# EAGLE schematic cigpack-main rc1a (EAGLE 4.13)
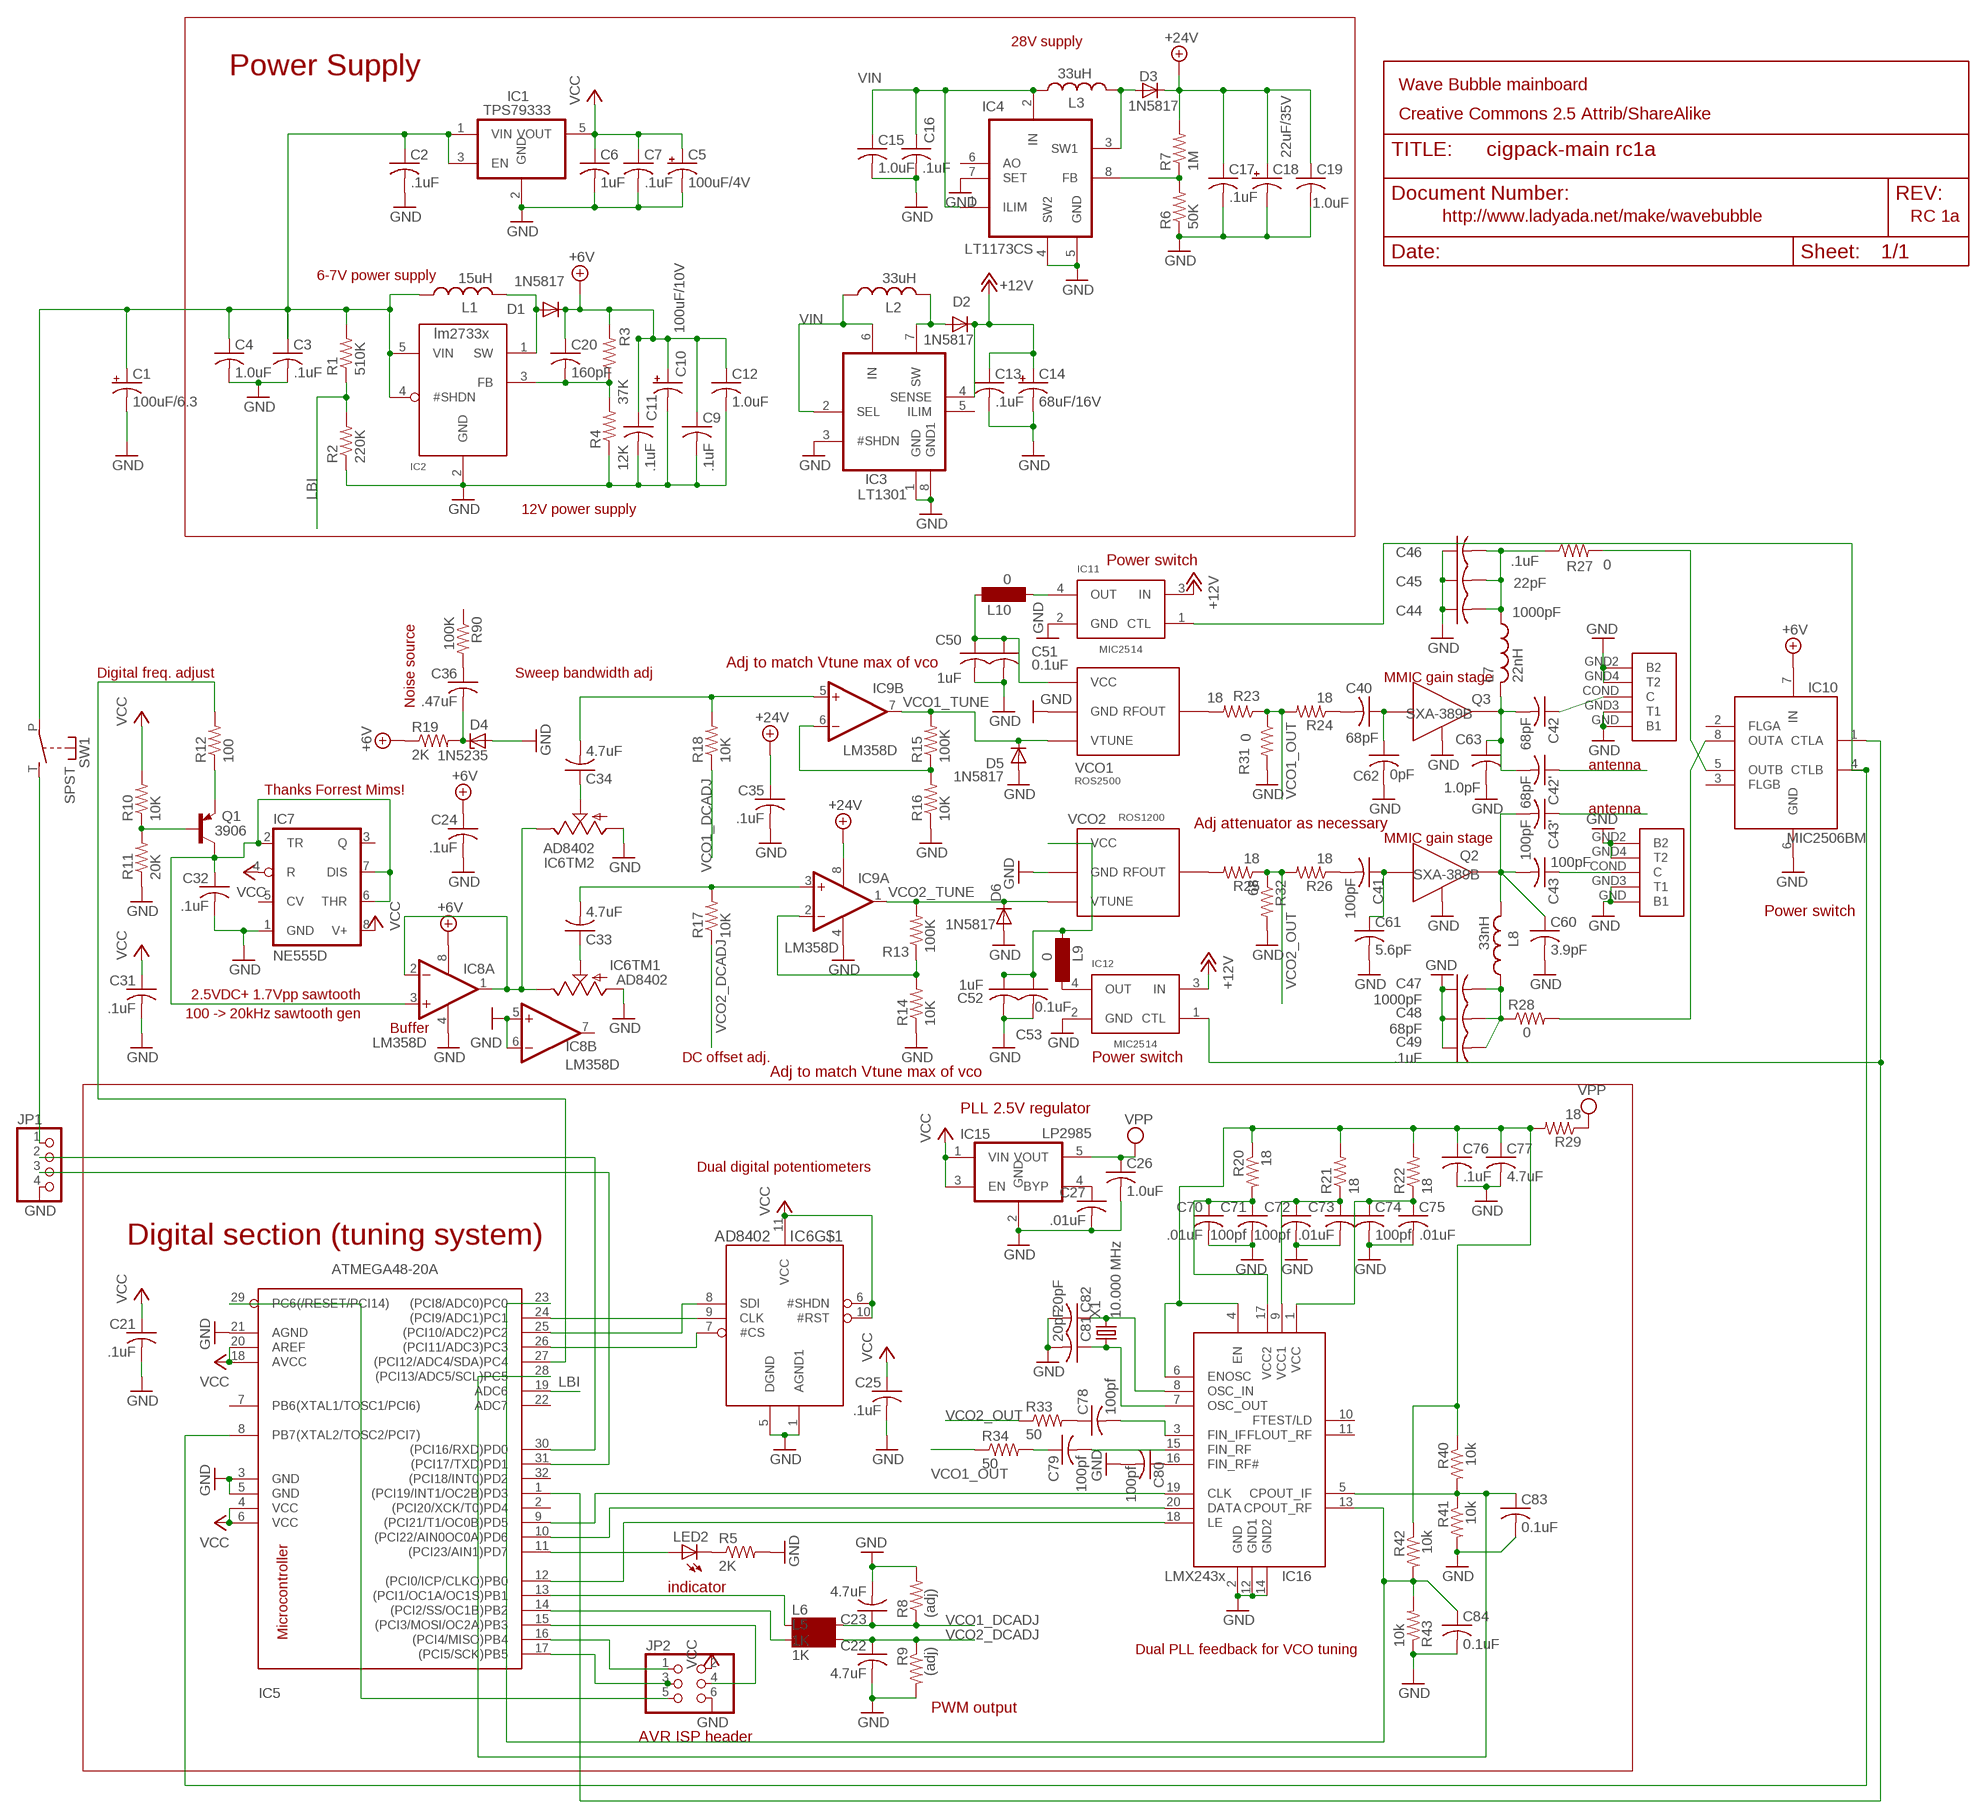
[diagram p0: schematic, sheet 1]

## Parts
C1  100uF/6.3  CPOL-USD  [PANASONIC_D]
C2  .1uF  C-USC1206  [C1206]
C3  .1uF  C-USC1206  [C1206]
C4  1.0uF  C-USC1206  [C1206]
C5  100uF/4V  CPOL-USD  [PANASONIC_D]
C6  1uF  C-USC1206  [C1206]
C7  .1uF  C-USC1206  [C1206]
C9  .1uF  C-USC1206  [C1206]
C10  100uF/10V  CPOL-USCT7343  [CT7343]
C11  .1uF  C-USC1206  [C1206]
C12  1.0uF  C-USC1206  [C1206]
C13  .1uF  C-USC1206  [C1206]
C14  68uF/16V  CPOL-USCT6032  [CT6032]
C15  1.0uF  C-USC1206  [C1206]
C16  .1uF  C-USC1206  [C1206]
C17  .1uF  C-USC1206  [C1206]
C18  22uF/35V  CPOL-USD/7343-31W  [D/7343-31W]
C19  1.0uF  C-USC1206  [C1206]
C20  160pF  C-USC1206  [C1206]
C21  .1uF  C-USC1206  [C1206]
C22  4.7uF  C-USC1206  [C1206]
C23  4.7uF  C-USC1206  [C1206]
C24  .1uF  C-USC1206  [C1206]
C25  .1uF  C-USC1206  [C1206]
C26  1.0uF  C-USC1206  [C1206]
C27  .01uF  C-USC0603  [C0603]
C31  .1uF  C-USC0603  [C0603]
C32  .1uF  C-USC1206  [C1206]
C33  4.7uF  C-USC1206  [C1206]
C34  4.7uF  C-USC1206  [C1206]
C35  .1uF  C-USC1206  [C1206]
C36  .47uF  C-USC1206  [C1206]
C40  68pF  C-USC0603  [C0603]
C41  100pF  C-USC0603  [C0603]
C42  68pF  C-USC0603  [C0603]
C42'  68pF  C-USC0603  [C0603]
C43  100pF  C-USC0603  [C0603]
C43'  100pF  C-USC0603  [C0603]
C44  1000pF  C-USC0603  [C0603]
C45  22pF  C-USC0603  [C0603]
C46  .1uF  C-USC1206  [C1206]
C47  1000pF  C-USC0603  [C0603]
C48  68pF  C-USC0603  [C0603]
C49  .1uF  C-USC1206  [C1206]
C50  1uF  C-USC1206  [C1206]
C51  0.1uF  C-USC1206  [C1206]
C52  1uF  C-USC1206  [C1206]
C53  0.1uF  C-USC1206  [C1206]
C60  3.9pF  C-USC0603  [C0603]
C61  5.6pF  C-USC0603  [C0603]
C62  0pF  C-USC0603  [C0603]
C63  1.0pF  C-USC0603  [C0603]
C70  .01uF  C-USC0603  [C0603]
C71  100pf  C-USC0603  [C0603]
C72  100pf  C-USC0603  [C0603]
C73  .01uF  C-USC0603  [C0603]
C74  100pf  C-USC0603  [C0603]
C75  .01uF  C-USC0603  [C0603]
C76  .1uF  C-USC0603  [C0603]
C77  4.7uF  C-USC0603  [C0603]
C78  100pf  C-USC0603  [C0603]
C79  100pf  C-USC0603  [C0603]
C80  100pf  C-USC0603  [C0603]
C81  20pF  C-USC0603  [C0603]
C82  20pF  C-USC0603  [C0603]
C83  0.1uF  C-USC1206  [C1206]
C84  0.1uF  C-USC1206  [C1206]
D1  1N5817  DIODE-SMB  [SMB]
D2  1N5817  DIODE-SMB  [SMB]
D3  1N5817  DIODE-SMB  [SMB]
D4  1N5235  ZENER-DIODESMB  [SMB]
D5  1N5817  DIODE-SMB  [SMB]
D6  1N5817  DIODE-SMB  [SMB]
IC1  TPS79333  TPS79XXX  [SOT23-5L]
IC2  LM2733  [SOT23-5L]
IC3  LT1301  [SO08]
IC4  LT1173CS  [SO08]
IC5  ATMEGA48-20A  [TQFP32-08]
IC6  AD8402  [SO14]
IC7  NE555D  [SO08]
IC8  LM358D  [SO08]
IC9  LM358D  [SO08]
IC10  MIC2506BM  [SO08]
IC11  MIC2514  [SOT23-5L]
IC12  MIC2514  [SOT23-5L]
IC15  LP2985  [SOT23-5L]
IC16  LMX243X  [TSSOP-20]
JP1  PINHD-1X4  [1X04]
JP2  PINHD-2X3  [2X03]
L1  15uH  L_CDRH  [CDRH6D28]
L2  33uH  L_CDRH  [CDRH6D28]
L3  33uH  L_CDRH  [CDRH6D28]
L5  1K  SM-1206  [SM-1206]
L6  1K  SM-1206  [SM-1206]
L7  22nH  L_0603  [0603]
L8  33nH  L_0603  [0603]
L9  0  SM-1206  [SM-1206]
L10  0  SM-1206  [SM-1206]
LED2  LEDCHIPLED_1206  [CHIPLED_1206]
Q1  3906  MMBT3906LT1SMD  [SOT23-BEC]
Q2  SXA-389B  MMIC_MIDPOWERGAIN  [SOT89]
Q3  SXA-389B  MMIC_MIDPOWERGAIN  [SOT89]
R1  510K  R-US_R1206  [R1206]
R2  220K  R-US_R1206  [R1206]
R3  37K  R-US_R1206  [R1206]
R4  12K  R-US_R1206  [R1206]
R5  2K  R-US_R1206  [R1206]
R6  50K  R-US_R1206  [R1206]
R7  1M  R-US_R1206  [R1206]
R8  (adj)  R-US_R1206  [R1206]
R9  (adj)  R-US_R1206  [R1206]
R10  10K  R-US_R1206  [R1206]
R11  20K  R-US_R1206  [R1206]
R12  100  R-US_R1206  [R1206]
R13  100K  R-US_R1206  [R1206]
R14  10K  R-US_R1206  [R1206]
R15  100K  R-US_R1206  [R1206]
R16  10K  R-US_R1206  [R1206]
R17  10K  R-US_R1206  [R1206]
R18  10K  R-US_R1206  [R1206]
R19  2K  R-US_R1206  [R1206]
R20  18  R-US_R0603  [R0603]
R21  18  R-US_R0603  [R0603]
R22  18  R-US_R0603  [R0603]
R23  18  R-US_R0603  [R0603]
R24  18  R-US_R0603  [R0603]
R25  18  R-US_R0603  [R0603]
R26  18  R-US_R0603  [R0603]
R27  0  R-US_M1206  [M1206]
R28  0  R-US_M1206  [M1206]
R29  18  R-US_R0603  [R0603]
R31  0  R-US_R0603  [R0603]
R32  68  R-US_R0603  [R0603]
R33  50  R-US_R0603  [R0603]
R34  50  R-US_R0603  [R0603]
R40  10k  R-US_R0603  [R0603]
R41  10k  R-US_R1206  [R1206]
R42  10k  R-US_R0603  [R0603]
R43  10k  R-US_R1206  [R1206]
R90  100K  R-US_R1206  [R1206]
SW1  SPST  [JUDCOSPST]
U$8  SMAANTENNA  [SMA-ANTENNA]
U$9  SMAANTENNA  [SMA-ANTENNA]
VCO1  ROS2500  VCOKG  [MINICIRCUITS_KG]
VCO2  ROS1200  VCOKG  [MINICIRCUITS_KG]
X1  10.000 MHz  CRYSTAL_CRYTALABMM  [ABMM]

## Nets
+6V: C9.1 C10.+ C11.1 C12.1 C20.1 C24.1 D1.C IC8.8(P:V+) IC10.7(IN) R3.2 R19.1
+12V: C13.1 C14.+ D2.C IC3.4(SENSE) IC11.3(IN) IC12.3(IN)
+24V: C17.1 C18.+ C19.1 C35.1 D3.C IC9.8(P:V+) R7.2
CLK: IC5.24((PCI9/ADC1)PC1) IC6.9(CLK)
CP_IF: C83.1 IC5.28((PCI13/ADC5/SCL)PC5) IC16.5(CPOUT_IF) R40.2 R41.1
CP_RF: C84.1 IC5.23((PCI8/ADC0)PC0) IC16.13(CPOUT_RF) R42.2 R43.2
FB: IC4.8(FB) R6.2 R7.1
GND: C1.- C2.2 C3.2 C4.2 C5.- C6.2 C7.2 C9.2 C10.- C11.2 C12.2 C13.2 C14.- C15.2 C16.2 C17.2 C18.- C19.2 C21.2 C22.2 C23.2 C24.2 C25.2 C26.2 C27.2 C31.2 C32.2 C35.2 C44.1 C45.1 C46.1 C47.1 C48.1 C49.1 C50.2 C51.2 C52.2 C53.2 C60.2 C61.2 C62.2 C63.2 C70.2 C71.2 C72.2 C73.2 C74.2 C75.2 C76.2 C77.2 C80.2 C81.2 C82.2 C83.2 C84.2 D4.A D5.A D6.A IC1.2(GND) IC2.2(GND) IC3.1(GND) IC3.3(#SHDN) IC3.8(GND1) IC4.4(SW2) IC4.5(GND) IC4.7(SET) IC5.3(GND) IC5.5(GND) IC5.21(AGND) IC6.1(AGND1) IC6.2(TM2:B) IC6.5(DGND) IC6.14(TM1:B) IC7.1(GND) IC8.4(P:V-) IC8.5(B:+IN) IC8.6(B:-IN) IC9.4(P:V-) IC10.6(GND) IC11.2(GND) IC12.2(GND) IC15.2(GND) IC16.2(GND) IC16.12(GND1) IC16.14(GND2) JP1.4 JP2.6 Q2.2(GND) Q3.2(GND) R2.1 R4.1 R5.2 R6.1 R8.2 R9.2 R11.1 R14.1 R16.1 R31.2 R32.2 R41.2 R43.1 U$8.GND2(B2) U$8.GND3(T1) U$8.GND4(T2) U$8.GND(B1) U$9.GND2(B2) U$9.GND3(T1) U$9.GND4(T2) U$9.GND(B1) VCO1.P$1(GND) VCO2.P$1(GND)
LBI: IC5.19(ADC6) R1.1 R2.2
MISO: IC5.16((PCI4/MISO)PB4) JP2.1
N$1: IC5.26((PCI11/ADC3)PC3) IC6.7(#CS)
N$2: D1.A IC2.1(SW) L1.L2
N$3: IC5.11((PCI23/AIN1)PD7) LED2.A
N$5: C36.2 D4.C R19.2
N$6: C78.1 R33.2
N$7: IC5.14((PCI2/SS/OC1B)PB2) L5.1
N$8: IC5.1((PCI19/INT1/OC2B)PD3) IC10.1(CTLA) IC12.1(CTL)
N$9: IC5.13((PCI1/OC1A/OC1S)PB1) L6.1
N$10: D2.A IC3.7(SW) L2.L2
N$11: Q1.B R10.1 R11.2
N$12: C32.1 IC7.2(TR) IC7.6(THR) IC7.7(DIS) IC8.3(A:+IN) Q1.C
N$13: Q1.E R12.1
N$14: C41.1 C61.1 Q2.1(RF_IN)
N$15: IC6.3(TM2:A) IC6.13(TM1:A) IC8.1(A:OUT) IC8.2(A:-IN)
N$16: C33.2 IC9.3(A:+IN) R17.2
N$17: C40.1 C62.1 Q3.1(RF_IN)
N$18: IC9.2(A:-IN) R13.1 R14.2
N$19: D3.A IC4.3(SW1) L3.L2
N$20: IC5.17((PCI5/SCK)PB5) JP2.3
N$21: C33.1 IC6.12(TM1:W)
N$22: IC9.6(B:-IN) R15.1 R16.2
N$23: IC11.4(OUT) L10.1
N$24: C34.1 IC6.4(TM2:W)
N$25: C79.1 R34.2
N$26: C44.2 C45.2 C46.2 L7.1 R27.1
N$27: IC10.8(OUTA) R28.2
N$28: C34.2 IC9.5(B:+IN) R18.2
N$29: C50.1 C51.1 L10.2 VCO1.P$14(VCC)
N$30: C52.1 C53.1 L9.1 VCO2.P$14(VCC)
N$31: C36.1 R90.2
N$32: C47.2 C48.2 C49.2 L8.1 R28.1
N$33: IC12.4(OUT) L9.2
N$34: IC5.15((PCI3/MOSI/OC2A)PB3) JP2.4
N$35: C82.1 IC16.8(OSC_IN) X1.X2
N$35R: C43'.2 C43.2 C60.1 L8.2 Q2.3(OUT)
N$37: C80.1 IC16.16(FIN_RF#)
N$39: C27.1 IC15.4(BYP)
N$40: C76.1 C77.1 IC16.4(EN) IC16.6(ENOSC) R20.1 R21.2 R22.2 R29.2 R40.1 R42.1
N$41: R23.2 VCO1.P$10(RFOUT)
N$42: C40.2 R24.1
N$43: C42'.2 C42.2 C63.1 L7.2 Q3.3(OUT)
N$45: IC5.27((PCI12/ADC4/SDA)PC4) R12.2
N$46: C78.2 IC16.3(FIN_IF)
N$47: R25.2 VCO2.P$10(RFOUT)
N$49: C41.2 R26.1
N$52: C79.2 IC16.15(FIN_RF)
N$57: JP1.1 SW1.T(S)
N$58: IC10.5(OUTB) R27.2
N$60: LED2.C R5.1
N$664: IC5.8(PB7(XTAL2/TOSC2/PCI7)) IC10.4(CTLB) IC11.1(CTL)
N$666: C81.1 IC16.7(OSC_OUT) X1.X1
N$10077: C74.1 C75.1 IC16.1(VCC) R22.1
PLL_CLK: IC5.9((PCI21/T1/OC0B)PD5) IC16.19(CLK)
PLL_DATA: IC5.10((PCI22/AIN0OC0A)PD6) IC16.20(DATA)
PLL_LE: IC5.12((PCI0/ICP/CLKO)PB0) IC16.18(LE)
RESET: IC5.29(PC6(/RESET/PCI14)) JP2.5
RF_OUT: C43.1 U$8.COND(C)
RF_OUT1: C42.1 U$9.COND(C)
RX: IC5.30((PCI16/RXD)PD0) JP1.2
SDI: IC5.25((PCI10/ADC2)PC2) IC6.8(SDI)
SENSE: C20.2 IC2.3(FB) R3.1 R4.2
STRIPLINE1: C42'.1
STRIPLINE2: C43'.1
TX: IC5.31((PCI17/TXD)PD1) JP1.3
VCC: C5.+ C6.1 C7.1 C21.1 C25.1 C31.1 IC1.5(VOUT) IC5.4(VCC) IC5.6(VCC) IC5.18(AVCC) IC5.20(AREF) IC6.6(#SHDN) IC6.10(#RST) IC6.11(VCC) IC7.4(R) IC7.8(V+) IC15.1(VIN) IC15.3(EN) JP2.2 R10.2
VCC1: C72.1 C73.1 IC16.9(VCC1) R21.1
VCC2: C70.1 C71.1 IC16.17(VCC2) R20.2
VCO1_DCADJ: C23.1 L6.2 R8.1 R18.1
VCO1_OUT: R23.1 R24.2 R31.1 R34.1
VCO1_TUNE: D5.C IC9.7(B:OUT) R15.2 VCO1.P$2(VTUNE)
VCO2_DCADJ: C22.1 L5.2 R9.1 R17.1
VCO2_OUT: R25.1 R26.2 R32.1 R33.1
VCO2_TUNE: D6.C IC9.1(A:OUT) R13.2 VCO2.P$2(VTUNE)
VIN: C1.+ C2.1 C3.1 C4.1 C15.1 C16.1 IC1.1(VIN) IC1.3(EN) IC2.4(#SHDN) IC2.5(VIN) IC3.2(SEL) IC3.6(IN) IC4.1(ILIM) IC4.2(IN) L1.L1 L2.L1 L3.L1 R1.2 SW1.P
VPP: C26.1 IC15.5(VOUT) R29.1
Unconnected: IC3.5(ILIM) IC4.6(AO) IC5.2((PCI20/XCK/T0)PD4) IC5.7(PB6(XTAL1/TOSC1/PCI6)) IC5.22(ADC7) IC5.32((PCI18/INT0)PD2) IC7.3(Q) IC7.5(CV) IC8.7(B:OUT) IC10.2(FLGA) IC10.3(FLGB) IC16.10(FTEST/LD) IC16.11(FLOUT_RF) R90.1

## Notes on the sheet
- 28V supply
- Power Supply
- Wave Bubble mainboard
- Creative Commons 2.5 Attrib/ShareAlike
- http://www.ladyada.net/make/wavebubble | RC 1a
- 6-7V power supply
- 12V power supply
- Power switch
- Noise source
- Digital freq. adjust | Sweep bandwidth adj | Adj to match Vtune max of vco
- MMIC gain stage
- antenna
- Thanks Forrest Mims!
- antenna
- Adj attenuator as necessary
- MMIC gain stage
- Power switch
- 2.5VDC+ 1.7Vpp sawtooth
- 100 -> 20kHz sawtooth gen
- Buffer
- DC offset adj. | Power switch
- Adj to match Vtune max of vco
- PLL 2.5V regulator
- Dual digital potentiometers
- Digital section (tuning system)
- indicator
- Microcontroller
- Dual PLL feedback for VCO tuning
- PWM output
- AVR ISP header

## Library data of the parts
C1 C5 C10 C14 C18 = rcl:CPOL-US: POLARIZED CAPACITOR, American symbol
C2-C4 C6 C7 C9 C11-C13 C15-C17 C19-C27 C31-C36 C40-C42 C42' C43 C43' C44-C53 C60-C63 C70-C84 = rcl:C-US: CAPACITOR, American symbol
D1-D3 D5 D6 = diode:DIODE-: DIODE
D4 = diode:ZENER-DIODE: Z-Diode
IC1 = cleanair:TPS79XXX
IC2 = cleanair:LM2733
IC3 = cleanair:LT1301
IC4 = cleanair:LT1173
IC5 = avr:ATMEGA48: MICROCONTROLLER 4 Kbytes FLASH 512 Bytes SRAM 256 Bytes EEPROM USART 8-channel 10 bit ADC
IC6 = cleanair:AD8402
IC7 = linear:*555: TIMER
IC8 IC9 = linear:LM358: OP AMP
IC10 = cleanair:MIC2506
IC11 IC12 = cleanair:MIC2514
IC15 = cleanair:LP2985
IC16 = cleanair:LMX243X
JP1 = pinhead:PINHD-1X4: PIN HEADER
JP2 = pinhead:PINHD-2X3: PIN HEADER
L1-L3 = cleanair:L
L5 L6 L9 L10 = inductor-neosid:SM-1206: INDUCTOR
L7 L8 = cleanair:L_0603
LED2 = led:LED: LED
Q1 = transistor-pnp:MMBT3906*: PNP Transistror
Q2 Q3 = cleanair:MMIC_MIDPOWERGAIN
R1-R29 R31-R34 R40-R43 R90 = rcl:R-US_: RESISTOR, American symbol
SW1 = cigpack-main_rc1:SPST
U$8 U$9 = cleanair:SMA
VCO1 VCO2 = cleanair:VCO
X1 = cigpack-main_rc1:CRYSTAL_CRYTAL: CRYSTAL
